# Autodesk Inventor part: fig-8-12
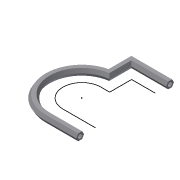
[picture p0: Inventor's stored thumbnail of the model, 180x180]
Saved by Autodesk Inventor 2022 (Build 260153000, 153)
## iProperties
Created: 2004-05
Part Number: fig-8-12
Document SubType Name: Modeling
Designer: CADCIM Technologies
Manufacturer: Standard
Standards Organization: Custom
Density: 1 g/cm^3
Material: Generic
Appearance: Default
Author: CADCIM Technologies
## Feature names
1. Sweep5
## Parameters: d4 = 0, d5 = 0
